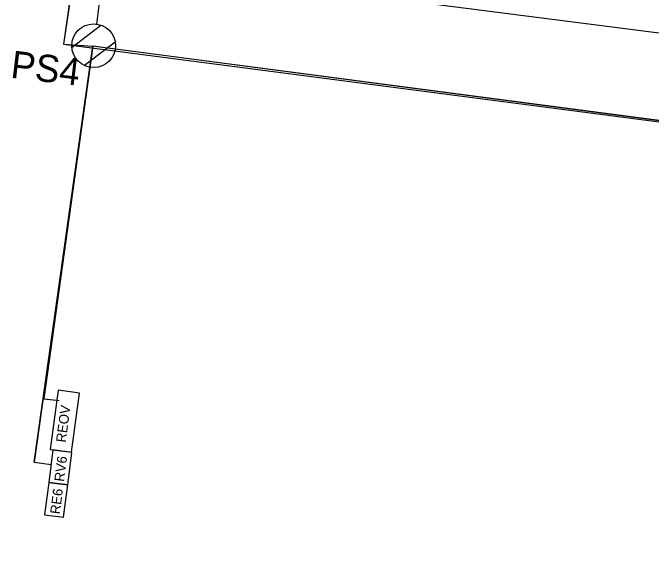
# Model space of a CAD drawing. Extents: x -669661 to -669105, y -977202 to -977030.
# Drawn here: x -669176.606 to -669176.021, y -977098.402 to -977097.887 of the extents above; entities that cross this region are included whole.
import ezdxf

# ---------------------------------------------------------------- set-up
doc = ezdxf.new("R2010")
doc.units = 0
doc.layers.add('Schéma', color=7, linetype='Continuous')

msp = doc.modelspace()

# ---------------------------------------------------------------- linework, layer by layer
at = {"layer": 'Schéma'}
for p, q in [((-669176.46756, -977097.26339), (-669176.5596, -977097.91565)), ((-669176.53301, -977097.73331), (-669176.5596, -977097.91565)), ((-669176.51985, -977097.82291), (-669176.52951, -977097.89729)), ((-669176.48705, -977097.8445), (-669175.77267, -977097.93615)), ((-669176.55189, -977097.91858), (-669176.52561, -977097.89835)), ((-669176.5596, -977097.91565), (-669172.93876, -977098.38798)), ((-669176.5596, -977097.91565), (-669176.53279, -977097.91763)), ((-669176.54051, -977097.93504), (-669176.5125, -977097.91346)), ((-669176.53326, -977097.9176), (-669176.58685, -977098.29878)), ((-669176.53326, -977097.9176), (-669176.5867, -977098.29869)), ((-669176.53279, -977097.91763), (-669176.57764, -977098.24069)), ((-669176.53279, -977097.91766), (-669176.57764, -977098.24069)), ((-669172.93876, -977098.38798), (-669176.53326, -977097.9176)), ((-669172.93876, -977098.38798), (-669176.53326, -977097.9176)), ((-669172.84309, -977098.40244), (-669176.53279, -977097.91766)), ((-669176.56475, -977098.2329), (-669176.57202, -977098.28716)), ((-669176.54514, -977098.23553), (-669176.56475, -977098.2329)), ((-669176.55242, -977098.28979), (-669176.54514, -977098.23553)), ((-669176.57764, -977098.24069), (-669176.56382, -977098.24224)), ((-669176.57764, -977098.24069), (-669176.56597, -977098.242)), ((-669176.56945, -977098.28762), (-669176.57325, -977098.31738)), ((-669176.57202, -977098.28716), (-669176.55242, -977098.28979)), ((-669176.55209, -977098.28984), (-669176.56945, -977098.28762)), ((-669176.55589, -977098.3196), (-669176.55209, -977098.28984)), ((-669176.5867, -977098.29869), (-669176.57101, -977098.30108)), ((-669176.57325, -977098.31738), (-669176.57705, -977098.34714)), ((-669176.55589, -977098.3196), (-669176.57325, -977098.31738)), ((-669176.57325, -977098.31738), (-669176.55589, -977098.3196)), ((-669176.55969, -977098.34935), (-669176.55589, -977098.3196)), ((-669176.57705, -977098.34714), (-669176.55969, -977098.34935))]:
    msp.add_line(p, q, dxfattribs=at)
msp.add_circle((-669176.53209, -977097.91712), 0.02, dxfattribs=at)

# ---------------------------------------------------------------- texts
for s, height, rotation, p in [('PS4', 0.025, 353.1527, (-669176.60898, -977097.94632)), ('REOV', 0.009, 82.36502, (-669176.55775, -977098.28114)), ('RV6', 0.009, 82.72693, (-669176.55932, -977098.31709)), ('RE6', 0.009, 82.72693, (-669176.56312, -977098.34685))]:
    msp.add_text(s, height=height, rotation=rotation, dxfattribs=at).set_placement(p)

doc.saveas('drawing.dxf')
